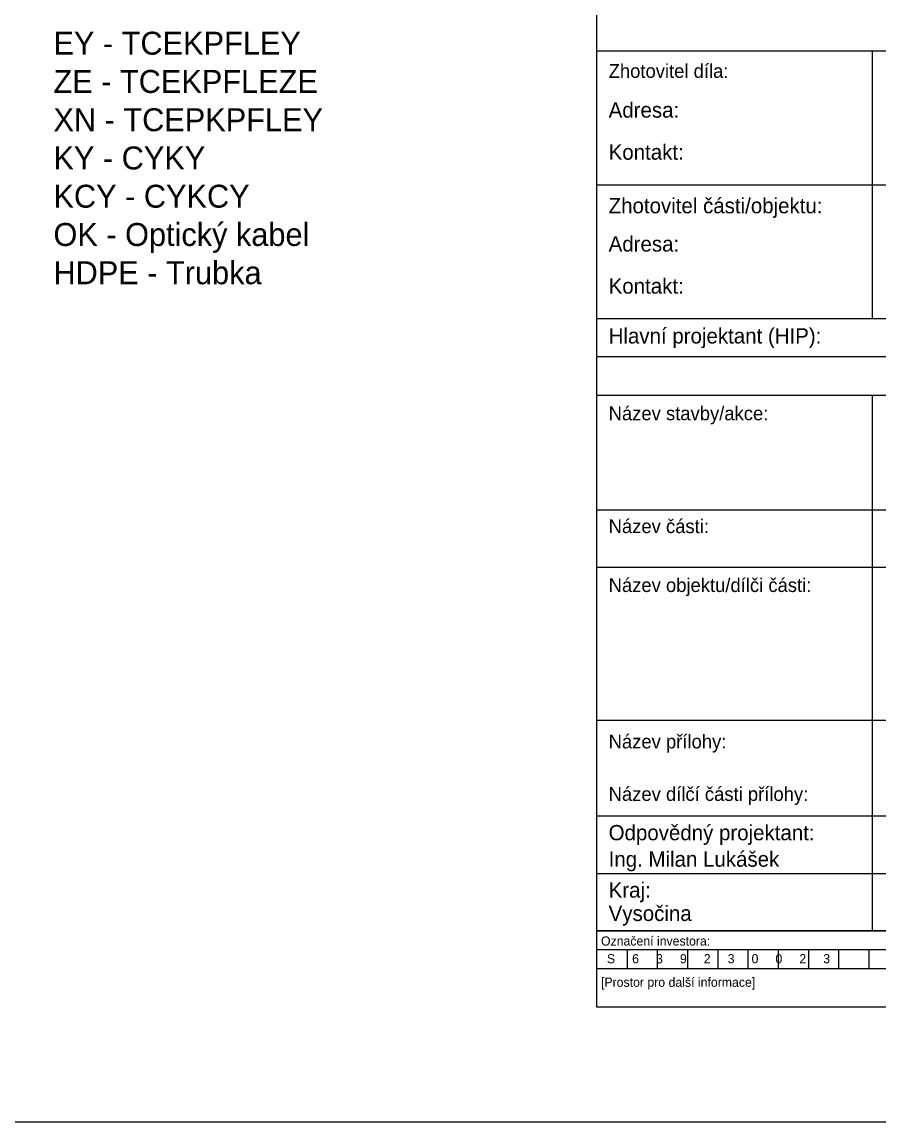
# Model space of a CAD drawing. Extents: x -650084 to -649664, y -1160055 to -1159758.
# Drawn here: x -649929.1 to -649817.1, y -1160054.5 to -1159910.7 of the extents above; entities that cross this region are included whole.
import ezdxf

# ---------------------------------------------------------------- set-up
doc = ezdxf.new("R2010")
doc.units = 0
for name, color, linetype in [('Rozpiska_pole_1', 7, 'Continuous'), ('Rozpiska_pole_6', 7, 'Continuous'), ('Rozpiska_pole_7', 7, 'Continuous'), ('Rozpiska_pole_8', 7, 'Continuous'), ('Rámečky-tisk', 7, 'Continuous'), ('Vrstva 1', 7, 'Continuous')]:
    doc.layers.add(name, color=color, linetype=linetype)

msp = doc.modelspace()

# ---------------------------------------------------------------- linework, layer by layer
at = {"layer": 'Rozpiska_pole_1'}
msp.add_lwpolyline([(-649854, -1159774.5), (-649684, -1159774.5), (-649684, -1160039.5), (-649854, -1160039.5)], close=True, dxfattribs=at)
at = {"layer": 'Rozpiska_pole_6'}
for p, q in [((-649817.95, -1159949.5), (-649817.95, -1159914.5)), ((-649854, -1159932), (-649684, -1159932)), ((-649854, -1159949.5), (-649684, -1159949.5))]:
    msp.add_line(p, q, dxfattribs=at)
msp.add_lwpolyline([(-649854, -1159914.5), (-649684, -1159914.5), (-649684, -1159954.5), (-649854, -1159954.5)], close=True, dxfattribs=at)
at = {"layer": 'Rozpiska_pole_7'}
for p, q in [((-649817.95, -1160029.5), (-649817.95, -1159959.5)), ((-649854, -1159974.5), (-649723.65, -1159974.5)), ((-649854, -1159982), (-649723.65, -1159982)), ((-649854, -1160002), (-649723.65, -1160002)), ((-649854, -1160014.5), (-649818.45, -1160014.5)), ((-649818.45, -1160014.5), (-649684.01, -1160014.5)), ((-649854, -1160022), (-649684.01, -1160022))]:
    msp.add_line(p, q, dxfattribs=at)
msp.add_lwpolyline([(-649854.01, -1159959.5), (-649684.01, -1159959.5), (-649684.01, -1160029.5), (-649854.01, -1160029.5)], close=True, dxfattribs=at)
at = {"layer": 'Rozpiska_pole_8'}
for p, q in [((-649684, -1160032), (-649854, -1160032)), ((-649850.05, -1160032), (-649850.05, -1160034.5)), ((-649846.1, -1160032), (-649846.1, -1160034.5)), ((-649842.15, -1160032), (-649842.15, -1160034.5)), ((-649838.2, -1160032), (-649838.2, -1160034.5)), ((-649834.25, -1160032), (-649834.25, -1160034.5)), ((-649830.3, -1160032), (-649830.3, -1160034.5)), ((-649826.35, -1160032), (-649826.35, -1160034.5)), ((-649822.4, -1160032), (-649822.4, -1160034.5)), ((-649818.45, -1160032), (-649818.45, -1160034.5))]:
    msp.add_line(p, q, dxfattribs=at)
msp.add_lwpolyline([(-649854, -1160029.5), (-649684, -1160029.5), (-649684, -1160034.5), (-649854, -1160034.5)], close=True, dxfattribs=at)
at = {"layer": 'Rámečky-tisk'}
msp.add_lwpolyline([(-650084, -1159757.5), (-650084, -1160054.5), (-649664, -1160054.5)], dxfattribs=at)

# ---------------------------------------------------------------- texts
at = {"layer": 'Rozpiska_pole_6'}
for s, height, p in [('Zhotovitel díla:', 1.8, (-649852.45, -1159918.03)), ('Adresa:', 2, (-649852.45, -1159923.23)), ('Kontakt:', 2, (-649852.45, -1159928.73)), ('Zhotovitel části/objektu:', 2, (-649852.45, -1159935.73)), ('Adresa:', 2, (-649852.45, -1159940.73)), ('Kontakt:', 2, (-649852.45, -1159946.23)), ('Hlavní projektant (HIP):', 2, (-649852.45, -1159952.75))]:
    msp.add_text(s, height=height, dxfattribs=at).set_placement(p)
at = {"layer": 'Rozpiska_pole_7'}
for s, height, p in [('Název stavby/akce:', 1.8, (-649852.45, -1159962.78)), ('Název části:', 1.8, (-649852.45, -1159977.53)), ('Název objektu/dílči části:', 1.8, (-649852.45, -1159985.23)), ('Název přílohy:', 1.8, (-649852.45, -1160005.67)), ('Název dílčí části přílohy:', 1.8, (-649852.45, -1160012.53)), ('Odpovědný projektant:', 2, (-649852.45, -1160017.68)), ('Ing. Milan Lukášek', 2, (-649852.45, -1160021.14)), ('Kraj:', 2, (-649852.45, -1160025.18)), ('Vysočina', 2, (-649852.45, -1160028.23))]:
    msp.add_text(s, height=height, dxfattribs=at).set_placement(p)
at = {"layer": 'Rozpiska_pole_8'}
for s, p in [('Označení investora:', (-649853.45, -1160031.44)), ('S     6     3     9     2     3     0     0     2     3 ', (-649852.68, -1160033.76)), ('[Prostor pro další informace]', (-649853.45, -1160036.83))]:
    msp.add_text(s, height=1.2, dxfattribs=at).set_placement(p)
at = {"layer": 'Vrstva 1'}
for s, p in [('EY - TCEKPFLEY', (-649925, -1159915)), ('ZE - TCEKPFLEZE', (-649925, -1159920)), ('XN - TCEPKPFLEY', (-649925, -1159925)), ('KY - CYKY', (-649925, -1159930)), ('KCY - CYKCY', (-649925, -1159935)), ('OK - Optický kabel', (-649925, -1159940)), ('HDPE - Trubka', (-649925, -1159945))]:
    msp.add_text(s, height=3, dxfattribs=at).set_placement(p)

doc.saveas('drawing.dxf')
